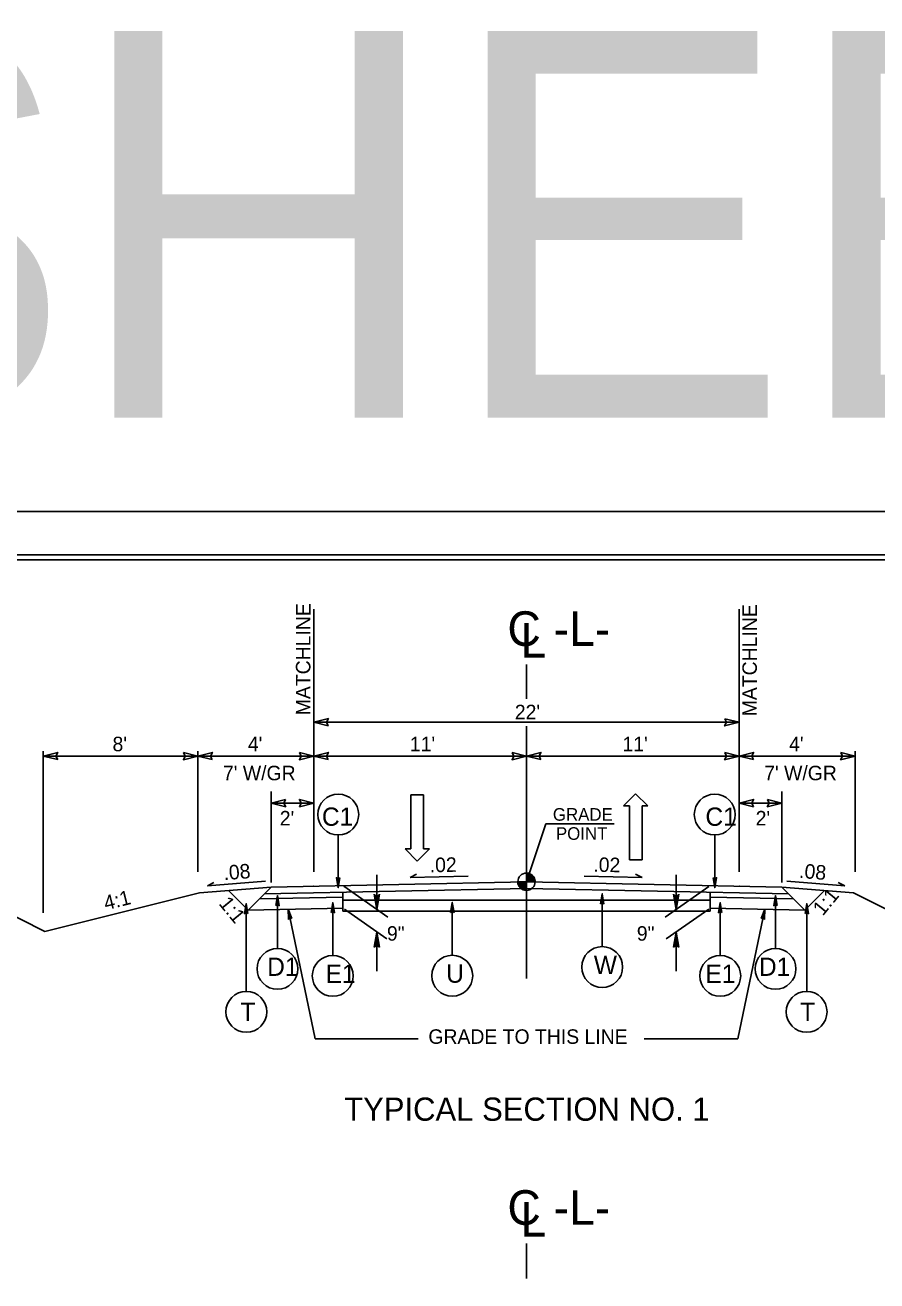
# Model space of a CAD drawing. Extents: x 575722 to 576066, y -53107 to -52774.
# Drawn here: x 575878.8 to 575922.9, y -52838.6 to -52773.6 of the extents above; entities that cross this region are included whole.
import ezdxf

# ---------------------------------------------------------------- set-up
doc = ezdxf.new("R2010")
doc.units = 0
for name, color, linetype in [('Prop Dimension Text', 7, 'Continuous'), ('Prop DSN Text', 7, 'Continuous'), ('Prop Lane Arrow CELL', 7, 'Continuous'), ('Prop Terminator CELL', 7, 'Continuous'), ('Sheet Cutting Line CELL', 7, 'Continuous'), ('Sheet Plot Border Inside CELL', 7, 'Continuous'), ('Sheet Plot Border Outside CELL', 7, 'Continuous'), ('Sheet Typical CELL', 7, 'Continuous'), ('Typical Grade Point Symbol CELL', 7, 'Continuous'), ('Typical ID Circle CELL', 7, 'Continuous'), ('Typical Pavement Slope CELL', 7, 'Continuous'), ('Typical Slope Point Local CELL', 7, 'Continuous'), ('Typical Terminator CELL', 7, 'Continuous'), ('Typical Text Centerline CELL', 7, 'Continuous'), ('Typical Text Grade Point CELL', 7, 'Continuous'), ('Typical Text ID Circle CELL', 7, 'Continuous')]:
    doc.layers.add(name, color=color, linetype=linetype)

# ---------------------------------------------------------------- blocks, each defined once
blk = doc.blocks.new('TERMINATOR')
at = {"layer": 'Typical Terminator CELL'}
blk.add_lwpolyline([(-0.469, 0.081), (0, 0), (-0.471, -0.083), (-0.411, 0)], close=True, dxfattribs=at)

msp = doc.modelspace()

# ---------------------------------------------------------------- linework, layer by layer
at = {"layer": 'Prop Dimension Text'}
for p, q in [((575893.77, -52817.391), (575893.77, -52803.808)), ((575915.77, -52817.391), (575915.77, -52803.808)), ((575915.77, -52809.664), (575893.77, -52809.664)), ((575879.77, -52819.522), (575879.77, -52811.161)), ((575887.77, -52816.911), (575887.77, -52811.161)), ((575887.77, -52817.391), (575887.77, -52811.161)), ((575893.77, -52817.391), (575893.77, -52811.161)), ((575893.77, -52816.911), (575893.77, -52811.161)), ((575893.77, -52816.911), (575893.77, -52811.161)), ((575893.77, -52816.911), (575893.77, -52811.161)), ((575915.77, -52817.391), (575915.77, -52811.161)), ((575915.77, -52816.911), (575915.77, -52811.161)), ((575915.77, -52816.911), (575915.77, -52811.161)), ((575915.77, -52816.911), (575915.77, -52811.161)), ((575921.77, -52817.391), (575921.77, -52811.161)), ((575921.77, -52816.911), (575921.77, -52811.161)), ((575887.77, -52811.411), (575879.77, -52811.411)), ((575893.77, -52811.411), (575887.77, -52811.411)), ((575904.77, -52811.411), (575893.77, -52811.411)), ((575904.77, -52811.411), (575915.77, -52811.411)), ((575915.77, -52811.411), (575921.77, -52811.411)), ((575891.563, -52817.949), (575891.563, -52813.237)), ((575891.563, -52813.843), (575893.77, -52813.843)), ((575917.976, -52813.843), (575915.77, -52813.843)), ((575917.976, -52817.949), (575917.976, -52813.237)), ((575890.376, -52819.377), (575889.361, -52818.362)), ((575890.376, -52819.377), (575891.568, -52818.185)), ((575893.758, -52818.142), (575893.762, -52818.147)), ((575915.782, -52818.142), (575915.777, -52818.147)), ((575919.163, -52819.377), (575917.971, -52818.185)), ((575919.163, -52819.377), (575920.178, -52818.362))]:
    msp.add_line(p, q, dxfattribs=at)
at = {"layer": 'Prop DSN Text'}
for p, q in [((575897.032, -52817.549), (575897.032, -52819.344)), ((575912.508, -52817.549), (575912.508, -52819.344)), ((575895.322, -52818.147), (575897.604, -52819.745)), ((575914.199, -52818.16), (575911.935, -52819.745)), ((575897.032, -52819.344), (575896.892, -52818.557)), ((575896.911, -52818.572), (575897.032, -52819.344)), ((575897.032, -52819.344), (575896.933, -52818.587)), ((575896.953, -52818.601), (575897.032, -52819.344)), ((575897.032, -52819.344), (575896.973, -52818.616)), ((575896.992, -52818.63), (575897.032, -52819.344)), ((575897.032, -52819.344), (575897.012, -52818.645)), ((575897.032, -52819.344), (575897.17, -52818.557)), ((575897.032, -52819.344), (575897.151, -52818.572)), ((575897.131, -52818.587), (575897.032, -52819.344)), ((575897.032, -52819.344), (575897.111, -52818.601)), ((575897.091, -52818.616), (575897.032, -52819.344)), ((575897.032, -52819.344), (575897.071, -52818.63)), ((575897.051, -52818.645), (575897.032, -52819.344)), ((575897.032, -52818.66), (575897.032, -52819.344)), ((575912.508, -52819.344), (575912.369, -52818.557)), ((575912.508, -52819.344), (575912.389, -52818.572)), ((575912.408, -52818.587), (575912.508, -52819.344)), ((575912.508, -52819.344), (575912.428, -52818.601)), ((575912.449, -52818.616), (575912.508, -52819.344)), ((575912.508, -52819.344), (575912.468, -52818.63)), ((575912.488, -52818.645), (575912.508, -52819.344)), ((575912.508, -52819.344), (575912.648, -52818.557)), ((575912.628, -52818.572), (575912.508, -52819.344)), ((575912.508, -52819.344), (575912.606, -52818.587)), ((575912.586, -52818.601), (575912.508, -52819.344)), ((575912.508, -52819.344), (575912.567, -52818.616)), ((575912.547, -52818.63), (575912.508, -52819.344)), ((575912.508, -52819.344), (575912.527, -52818.645)), ((575912.508, -52818.66), (575912.508, -52819.344)), ((575893.833, -52826.037), (575892.437, -52819.334)), ((575895.351, -52819.334), (575897.54, -52820.866)), ((575914.2, -52819.326), (575912, -52820.866)), ((575915.706, -52826.037), (575917.103, -52819.334)), ((575897.032, -52820.511), (575896.892, -52821.298)), ((575897.032, -52820.511), (575896.911, -52821.283)), ((575896.933, -52821.269), (575897.032, -52820.511)), ((575897.032, -52820.511), (575896.953, -52821.253)), ((575896.973, -52821.239), (575897.032, -52820.511)), ((575897.032, -52820.511), (575896.992, -52821.226)), ((575897.012, -52821.211), (575897.032, -52820.511)), ((575897.032, -52820.511), (575897.032, -52822.532)), ((575897.032, -52820.511), (575897.17, -52821.298)), ((575897.151, -52821.283), (575897.032, -52820.511)), ((575897.032, -52820.511), (575897.131, -52821.269)), ((575897.111, -52821.253), (575897.032, -52820.511)), ((575897.032, -52820.511), (575897.091, -52821.239)), ((575897.071, -52821.226), (575897.032, -52820.511)), ((575897.032, -52820.511), (575897.051, -52821.211)), ((575897.032, -52821.196), (575897.032, -52820.511)), ((575912.508, -52820.511), (575912.369, -52821.298)), ((575912.389, -52821.283), (575912.508, -52820.511)), ((575912.508, -52820.511), (575912.408, -52821.269)), ((575912.428, -52821.253), (575912.508, -52820.511)), ((575912.508, -52820.511), (575912.449, -52821.239)), ((575912.468, -52821.226), (575912.508, -52820.511)), ((575912.508, -52820.511), (575912.488, -52821.211)), ((575912.508, -52820.511), (575912.508, -52822.532)), ((575912.508, -52820.511), (575912.648, -52821.298)), ((575912.508, -52821.196), (575912.508, -52820.511)), ((575912.527, -52821.211), (575912.508, -52820.511)), ((575912.508, -52820.511), (575912.547, -52821.226)), ((575912.567, -52821.239), (575912.508, -52820.511)), ((575912.508, -52820.511), (575912.586, -52821.253)), ((575912.606, -52821.269), (575912.508, -52820.511)), ((575912.508, -52820.511), (575912.628, -52821.283)), ((575897.032, -52821.196), (575896.892, -52821.298)), ((575897.17, -52821.298), (575897.032, -52821.196)), ((575912.369, -52821.298), (575912.508, -52821.196)), ((575912.508, -52821.196), (575912.648, -52821.298)), ((575893.833, -52826.037), (575899.158, -52826.037)), ((575910.857, -52826.037), (575915.706, -52826.037))]:
    msp.add_line(p, q, dxfattribs=at)
at = {"layer": 'Prop Lane Arrow CELL'}
for p, q in [((575898.785, -52813.417), (575898.785, -52816.217)), ((575899.445, -52813.417), (575898.785, -52813.417)), ((575899.445, -52816.217), (575899.445, -52813.417)), ((575909.795, -52813.986), (575910.415, -52813.356)), ((575910.415, -52813.356), (575911.055, -52813.986)), ((575910.095, -52813.986), (575909.795, -52813.986)), ((575910.095, -52816.786), (575910.095, -52813.986)), ((575911.055, -52813.986), (575910.755, -52813.986)), ((575910.755, -52813.986), (575910.755, -52816.786)), ((575898.785, -52816.217), (575898.485, -52816.217)), ((575898.485, -52816.217), (575899.105, -52816.847)), ((575899.105, -52816.847), (575899.745, -52816.217)), ((575899.745, -52816.217), (575899.445, -52816.217)), ((575910.755, -52816.786), (575910.095, -52816.786))]:
    msp.add_line(p, q, dxfattribs=at)
at = {"layer": 'Prop Terminator CELL'}
for points in [[(575892.624, -52819.81), (575892.437, -52819.334), (575892.452, -52819.848), (575892.527, -52819.767)], [(575916.915, -52819.81), (575917.103, -52819.334), (575917.087, -52819.848), (575917.013, -52819.767)]]:
    msp.add_lwpolyline(points, close=True, dxfattribs=at)
at = {"layer": 'Sheet Cutting Line CELL'}
msp.add_line((575964.975, -52798.762), (575796.575, -52798.762), dxfattribs=at)
at = {"layer": 'Sheet Plot Border Inside CELL'}
msp.add_lwpolyline([(575964.525, -52801.007), (575797.875, -52801.007), (575797.875, -52906.517), (575964.525, -52906.517)], close=True, dxfattribs=at)
at = {"layer": 'Sheet Plot Border Outside CELL'}
msp.add_lwpolyline([(575964.975, -52798.762), (575796.575, -52798.762), (575796.575, -52908.762), (575964.975, -52908.762)], close=True, dxfattribs=at)
at = {"layer": 'Sheet Typical CELL'}
msp.add_lwpolyline([(575963.275, -52801.262), (575813.275, -52801.262), (575813.275, -52906.262), (575963.275, -52906.262)], close=True, dxfattribs=at)
at = {"layer": 'Typical Grade Point Symbol CELL'}
for p, q in [((575904.77, -52817.911), (575905.77, -52814.911)), ((575904.77, -52817.911), (575904.77, -52817.463)), ((575904.322, -52817.911), (575904.77, -52817.911)), ((575904.769, -52818.358), (575904.77, -52817.911)), ((575904.77, -52817.911), (575904.769, -52818.358)), ((575905.217, -52817.911), (575904.77, -52817.911))]:
    msp.add_line(p, q, dxfattribs=at)
for points in [[(575904.774, -52817.463), (575904.774, -52817.463), (575904.774, -52817.911)], [(575904.783, -52817.463), (575904.783, -52817.911)], [(575904.792, -52817.464), (575904.792, -52817.911)], [(575904.8, -52817.464), (575904.8, -52817.911)], [(575904.809, -52817.465), (575904.809, -52817.911)], [(575904.818, -52817.466), (575904.818, -52817.911)], [(575904.827, -52817.467), (575904.827, -52817.911)], [(575904.836, -52817.468), (575904.836, -52817.911)], [(575904.845, -52817.469), (575904.845, -52817.911)], [(575904.854, -52817.471), (575904.854, -52817.911)], [(575904.863, -52817.473), (575904.863, -52817.911)], [(575904.872, -52817.475), (575904.872, -52817.911)], [(575904.881, -52817.477), (575904.881, -52817.911)], [(575904.89, -52817.48), (575904.89, -52817.911)], [(575904.899, -52817.482), (575904.899, -52817.911)], [(575904.908, -52817.485), (575904.908, -52817.911)], [(575904.917, -52817.488), (575904.917, -52817.911)], [(575904.926, -52817.491), (575904.926, -52817.911)], [(575904.935, -52817.495), (575904.935, -52817.911)], [(575904.944, -52817.499), (575904.944, -52817.911)], [(575904.953, -52817.503), (575904.953, -52817.911)], [(575904.962, -52817.507), (575904.962, -52817.911)], [(575904.971, -52817.511), (575904.971, -52817.911)], [(575904.98, -52817.516), (575904.98, -52817.911)], [(575904.988, -52817.521), (575904.988, -52817.911)], [(575904.997, -52817.526), (575904.997, -52817.911)], [(575905.006, -52817.531), (575905.006, -52817.911)], [(575905.015, -52817.537), (575905.015, -52817.911)], [(575905.024, -52817.543), (575905.024, -52817.911)], [(575905.033, -52817.55), (575905.033, -52817.911)], [(575905.042, -52817.556), (575905.042, -52817.911)], [(575905.051, -52817.563), (575905.051, -52817.911)], [(575905.06, -52817.57), (575905.06, -52817.911)], [(575905.069, -52817.578), (575905.069, -52817.911)], [(575905.078, -52817.586), (575905.078, -52817.911)], [(575905.087, -52817.595), (575905.087, -52817.911)], [(575905.096, -52817.604), (575905.096, -52817.911)], [(575905.105, -52817.614), (575905.105, -52817.911)], [(575905.114, -52817.625), (575905.114, -52817.911)], [(575905.123, -52817.636), (575905.123, -52817.911)], [(575905.132, -52817.648), (575905.132, -52817.911)], [(575905.141, -52817.661), (575905.141, -52817.911)], [(575905.15, -52817.675), (575905.15, -52817.911)], [(575905.159, -52817.69), (575905.159, -52817.911)], [(575905.168, -52817.706), (575905.168, -52817.911)], [(575905.176, -52817.725), (575905.176, -52817.911)], [(575905.185, -52817.746), (575905.185, -52817.911)], [(575904.324, -52817.911), (575904.324, -52817.959)], [(575904.333, -52817.911), (575904.333, -52818.012)], [(575904.342, -52817.911), (575904.342, -52818.044)], [(575904.351, -52817.911), (575904.351, -52818.071)], [(575904.36, -52817.911), (575904.36, -52818.092)], [(575904.369, -52817.911), (575904.369, -52818.111)], [(575904.378, -52817.911), (575904.378, -52818.127)], [(575904.387, -52817.911), (575904.387, -52818.143)], [(575904.396, -52817.911), (575904.396, -52818.157)], [(575904.405, -52817.911), (575904.405, -52818.17)], [(575904.414, -52817.911), (575904.414, -52818.182)], [(575904.423, -52817.911), (575904.423, -52818.193)], [(575904.431, -52817.911), (575904.431, -52818.204)], [(575904.44, -52817.911), (575904.44, -52818.214)], [(575904.449, -52817.911), (575904.449, -52818.224)], [(575904.458, -52817.911), (575904.458, -52818.233)], [(575904.467, -52817.911), (575904.467, -52818.241)], [(575904.476, -52817.911), (575904.476, -52818.249)], [(575904.485, -52817.911), (575904.485, -52818.257)], [(575904.494, -52817.911), (575904.494, -52818.264)], [(575904.503, -52817.911), (575904.503, -52818.271)], [(575904.512, -52817.911), (575904.512, -52818.277)], [(575904.521, -52817.911), (575904.521, -52818.283)], [(575904.53, -52817.911), (575904.53, -52818.289)], [(575904.539, -52817.911), (575904.539, -52818.295)], [(575904.548, -52817.911), (575904.548, -52818.3)], [(575904.557, -52817.911), (575904.557, -52818.305)], [(575904.566, -52817.911), (575904.566, -52818.31)], [(575904.575, -52817.911), (575904.575, -52818.314)], [(575904.584, -52817.911), (575904.584, -52818.318)], [(575904.593, -52817.911), (575904.593, -52818.321)], [(575904.602, -52817.911), (575904.602, -52818.325)], [(575904.611, -52817.911), (575904.611, -52818.329)], [(575904.619, -52817.911), (575904.619, -52818.332)], [(575904.628, -52817.911), (575904.628, -52818.335)], [(575904.637, -52817.911), (575904.637, -52818.338)], [(575904.646, -52817.911), (575904.646, -52818.34)], [(575904.655, -52817.911), (575904.655, -52818.343)], [(575904.664, -52817.911), (575904.664, -52818.345)], [(575904.673, -52817.911), (575904.673, -52818.347)], [(575904.682, -52817.911), (575904.682, -52818.349)], [(575904.691, -52817.911), (575904.691, -52818.351)], [(575904.7, -52817.911), (575904.7, -52818.352)], [(575904.709, -52817.911), (575904.709, -52818.354)], [(575904.718, -52817.911), (575904.718, -52818.355)], [(575904.727, -52817.911), (575904.727, -52818.356)], [(575904.736, -52817.911), (575904.736, -52818.357)], [(575904.745, -52817.911), (575904.745, -52818.357)], [(575904.754, -52817.911), (575904.754, -52818.358)], [(575904.763, -52817.911), (575904.763, -52818.358), (575904.763, -52818.358)], [(575905.194, -52817.77), (575905.194, -52817.911)], [(575905.203, -52817.801), (575905.203, -52817.911)], [(575905.212, -52817.847), (575905.212, -52817.911)]]:
    msp.add_lwpolyline(points, dxfattribs=at)
msp.add_circle((575904.769, -52817.911), 0.448, dxfattribs=at)
for start, end in [(359.99048, 89.99048), (179.99048, 269.99048)]:
    msp.add_arc((575904.769, -52817.911), 0.448, start, end, dxfattribs=at)
at = {"layer": 'Typical ID Circle CELL'}
for p, q in [((575895.031, -52815.491), (575895.031, -52818.225)), ((575914.509, -52815.491), (575914.509, -52818.225)), ((575890.27, -52823.581), (575890.27, -52819.04)), ((575891.887, -52821.359), (575891.887, -52818.625)), ((575894.747, -52821.722), (575894.747, -52818.988)), ((575900.927, -52821.715), (575900.927, -52818.981)), ((575908.685, -52821.267), (575908.685, -52818.533)), ((575914.793, -52821.722), (575914.793, -52818.988)), ((575917.652, -52821.359), (575917.652, -52818.625)), ((575919.269, -52823.581), (575919.269, -52819.04))]:
    msp.add_line(p, q, dxfattribs=at)
for centre in [(575895.031, -52814.434), (575914.509, -52814.434), (575891.887, -52822.417), (575908.685, -52822.325), (575917.652, -52822.417), (575894.747, -52822.779), (575900.927, -52822.772), (575914.793, -52822.779), (575890.277, -52824.639), (575919.262, -52824.639)]:
    msp.add_circle(centre, 1.058, dxfattribs=at)
at = {"layer": 'Typical Pavement Slope CELL'}
for p, q in [((575898.749, -52817.685), (575899.082, -52817.518)), ((575901.749, -52817.622), (575898.749, -52817.685)), ((575907.749, -52817.622), (575910.749, -52817.685)), ((575910.749, -52817.685), (575910.416, -52817.518)), ((575891.568, -52818.185), (575887.857, -52818.482)), ((575891.267, -52817.885), (575888.267, -52818.125)), ((575888.267, -52818.125), (575888.6, -52817.958)), ((575917.971, -52818.185), (575921.682, -52818.482)), ((575918.231, -52817.885), (575921.231, -52818.125)), ((575921.231, -52818.125), (575920.898, -52817.958)), ((575895.267, -52818.458), (575895.267, -52819.275)), ((575895.267, -52818.862), (575895.267, -52819.429)), ((575914.272, -52818.458), (575914.272, -52819.275)), ((575914.272, -52818.862), (575914.272, -52819.429))]:
    msp.add_line(p, q, dxfattribs=at)
for points in [[(575904.77, -52818.261), (575891.21, -52818.543)], [(575904.77, -52817.911), (575891.568, -52818.185)], [(575904.77, -52817.911), (575917.971, -52818.185)], [(575904.77, -52818.261), (575918.329, -52818.543)], [(575895.267, -52818.708), (575890.955, -52818.798)], [(575895.267, -52818.862), (575914.272, -52818.862)], [(575914.272, -52818.708), (575918.584, -52818.798)], [(575895.267, -52819.275), (575890.376, -52819.377)], [(575895.267, -52819.429), (575914.272, -52819.429)], [(575914.272, -52819.275), (575919.163, -52819.377)]]:
    msp.add_lwpolyline(points, dxfattribs=at)
at = {"layer": 'Typical Slope Point Local CELL'}
for p, q in [((575871.929, -52816.517), (575879.858, -52820.482)), ((575887.857, -52818.482), (575879.858, -52820.482)), ((575932.845, -52824.064), (575921.682, -52818.482))]:
    msp.add_line(p, q, dxfattribs=at)
at = {"layer": 'Typical Terminator CELL'}
for points in [[(575895.119, -52817.71), (575895.031, -52818.225), (575894.939, -52817.707), (575895.031, -52817.773)], [(575914.42, -52817.71), (575914.509, -52818.225), (575914.6, -52817.707), (575914.509, -52817.773)], [(575890.359, -52819.556), (575890.27, -52819.04), (575890.179, -52819.559), (575890.27, -52819.493)], [(575891.798, -52819.141), (575891.887, -52818.625), (575891.979, -52819.144), (575891.887, -52819.078)], [(575894.658, -52819.503), (575894.747, -52818.988), (575894.838, -52819.506), (575894.747, -52819.44)], [(575900.839, -52819.496), (575900.927, -52818.981), (575901.019, -52819.499), (575900.927, -52819.433)], [(575908.597, -52819.048), (575908.685, -52818.533), (575908.777, -52819.051), (575908.685, -52818.985)], [(575914.881, -52819.503), (575914.793, -52818.988), (575914.701, -52819.506), (575914.793, -52819.44)], [(575917.741, -52819.141), (575917.652, -52818.625), (575917.561, -52819.144), (575917.652, -52819.078)], [(575919.18, -52819.556), (575919.269, -52819.04), (575919.361, -52819.559), (575919.269, -52819.493)]]:
    msp.add_lwpolyline(points, close=True, dxfattribs=at)
at = {"layer": 'Typical Text Centerline CELL'}
for p, q in [((575904.77, -52808.456), (575904.77, -52806.678)), ((575904.77, -52822.911), (575904.77, -52809.861)), ((575904.77, -52838.424), (575904.77, -52836.619))]:
    msp.add_line(p, q, dxfattribs=at)
at = {"layer": 'Typical Text Grade Point CELL'}
msp.add_line((575905.77, -52814.911), (575909.308, -52814.911), dxfattribs=at)

# ---------------------------------------------------------------- block references
at = {"layer": 'Prop Dimension Text', "xscale": 1.5906680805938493, "rotation": 180}
for p, yscale in [((575893.77, -52809.664), 2.2831050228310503), ((575879.77, -52811.411), 2.2831050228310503), ((575887.77, -52811.411), 2.2831050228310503), ((575893.77, -52811.411), 2.2831050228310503), ((575904.77, -52811.411), 2.2831050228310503), ((575915.77, -52811.411), 2.2831050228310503), ((575891.563, -52813.843), -2.2831050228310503), ((575915.77, -52813.843), 2.2831050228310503)]:
    msp.add_blockref('TERMINATOR', p, dxfattribs=dict(at, yscale=yscale))
at = {"layer": 'Prop Dimension Text', "xscale": 1.5906680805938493}
for p, yscale in [((575915.77, -52809.664), 2.2831050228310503), ((575887.77, -52811.411), 2.2831050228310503), ((575893.77, -52811.411), 2.2831050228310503), ((575904.77, -52811.411), 2.2831050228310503), ((575915.77, -52811.411), 2.2831050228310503), ((575921.77, -52811.411), 2.2831050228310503), ((575893.77, -52813.843), -2.2831050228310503), ((575917.976, -52813.843), 2.2831050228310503)]:
    msp.add_blockref('TERMINATOR', p, dxfattribs=dict(at, yscale=yscale))

# ---------------------------------------------------------------- texts
at = {"layer": 'Prop Dimension Text'}
for s, rotation, p in [('MATCHLINE', 89.89889, (575893.586, -52809.302)), ('MATCHLINE', 89.89889, (575916.684, -52809.356)), ('.08', 4.57392, (575889.124, -52817.831)), ('.02', 1.19158, (575899.771, -52817.423)), ('.02', 358.80842, (575908.221, -52817.393)), ('.08', 355.42608, (575918.853, -52817.709))]:
    msp.add_text(s, height=0.75, rotation=rotation, dxfattribs=at).set_placement(p)
for s, height, p in [("22'", 0.75, (575904.166, -52809.507)), ("8'", 0.75, (575883.354, -52811.161)), ("4'", 0.75, (575890.354, -52811.161)), ("11'", 0.75, (575898.737, -52811.161)), ("11'", 0.75, (575909.737, -52811.161)), ("4'", 0.75, (575918.354, -52811.161)), ("7' W/GR", 0.75, (575889.067, -52812.663)), ("7' W/GR", 0.75, (575917.067, -52812.663)), ("2'", 0.75, (575892.005, -52814.999)), ("2'", 0.75, (575916.625, -52814.999)), ('TYPICAL SECTION NO. 1', 1.2, (575895.337, -52830.273)), ('TYPICAL SECTION NO. 1', 1.2, (575895.337, -52830.273))]:
    msp.add_text(s, height=height, dxfattribs=at).set_placement(p)
at = {"layer": 'Prop DSN Text'}
for s, height, p in [('C -L-', 1.7897, (575903.782, -52805.714)), ('L', 1.79, (575904.459, -52806.321)), ('9" ', 0.75, (575897.551, -52820.959)), ('9" ', 0.75, (575910.477, -52820.959)), ('GRADE TO THIS LINE', 0.75, (575899.693, -52826.295)), ('C -L-', 1.7897, (575903.782, -52835.655)), ('L', 1.79, (575904.459, -52836.262))]:
    msp.add_text(s, height=height, dxfattribs=at).set_placement(p)
at = {"layer": 'Typical Pavement Slope CELL'}
msp.add_text('OPTIONAL SHEET LAYOUT', height=20, dxfattribs=at).set_placement((575720.738, -52793.902))
at = {"layer": 'Typical Slope Point Local CELL'}
for s, rotation, p in [('4:1', 14.03624, (575883.005, -52819.392)), ('1:1', 50.56619, (575920.099, -52819.714)), ('1:1', 309.43381, (575888.816, -52819.055))]:
    msp.add_text(s, height=0.75, rotation=rotation, dxfattribs=at).set_placement(p)
at = {"layer": 'Typical Text Grade Point CELL'}
for s, p in [('GRADE', (575906.134, -52814.755)), ('POINT', (575906.291, -52815.743))]:
    msp.add_text(s, height=0.6525, dxfattribs=at).set_placement(p)
at = {"layer": 'Typical Text ID Circle CELL'}
for s, height, p in [('C1', 0.9469, (575894.186, -52815.018)), ('C1', 0.9469, (575914.027, -52815.018)), ('D1', 0.9469, (575891.353, -52822.779)), ('E1', 0.9469, (575894.375, -52823.142)), ('U', 0.947, (575900.616, -52823.135)), ('W', 0.947, (575908.254, -52822.687)), ('E1', 0.9469, (575914.028, -52823.142)), ('D1', 0.9469, (575916.794, -52822.779)), ('T', 0.947, (575889.971, -52825.118)), ('T', 0.947, (575918.928, -52825.118))]:
    msp.add_text(s, height=height, dxfattribs=at).set_placement(p)

doc.saveas('drawing.dxf')
